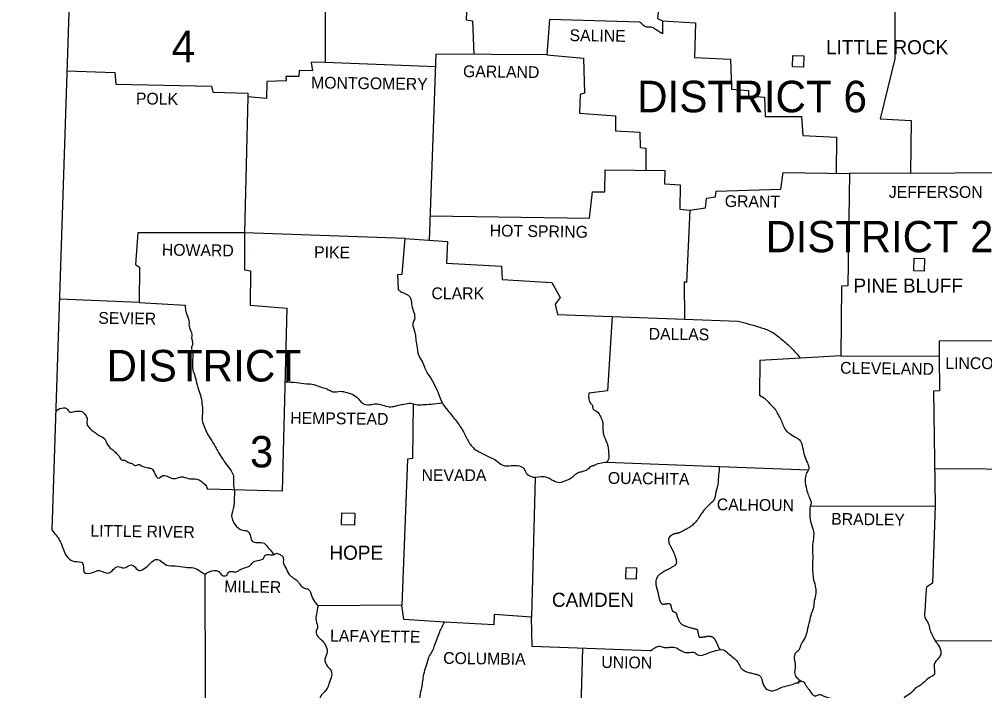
# Model space of a CAD drawing. Extents: x -819161 to 80911, y -6604 to 768454.
# Drawn here: x 48569 to 50478, y 6893 to 8220 of the extents above; entities that cross this region are included whole.
import ezdxf

# ---------------------------------------------------------------- set-up
doc = ezdxf.new("R2010")
doc.units = 0
doc.layers.add('Default', color=7, linetype='Continuous')
doc.layers.add('SHET_Border-Lines', color=7, linetype='Continuous')

msp = doc.modelspace()

# ---------------------------------------------------------------- linework, layer by layer
at = {"layer": 'Default'}
msp.add_line((48650, 7450.6), (48640.9, 7444.9), dxfattribs=at)
for points in [[(48569, 9606.7), (48682.3, 8696.4), (48633.2, 7210.7)], [(49174.7, 8359.8), (49174, 8135.6), (49146.3, 8135), (49148.8, 8118.8), (49122.4, 8119.1), (49121.8, 8107), (49095.9, 8107), (49096.5, 8098.6), (49058.6, 8097.3), (49057.6, 8064), (49020.6, 8067.4), (49014.4, 7797.9)], [(50267.6, 8353.4), (50299.4, 8351.6), (50300, 8142.1), (50271.4, 8023.6), (50332.4, 8020.5), (50331.4, 7916)], [(50014, 8298.7), (49974.8, 8303.3), (49976.3, 8288.4), (49904.4, 8285.6), (49902.3, 8264.4), (49834.7, 8260.7), (49831, 8222.1), (49841, 8217.1), (49841, 8191.9)], [(49453.5, 8234.3), (49452.6, 8219.3), (49465.3, 8217.1), (49467.6, 8150.7)], [(49795.8, 8215), (49617.2, 8220.2), (49612.2, 8149.9), (49392.8, 8151.2), (49379.3, 7783.7)], [(49841, 8217.1), (49906.3, 8213.1), (49903.8, 8144.6), (49975.4, 8141.8), (49977, 8082.1), (50010.6, 8079.3), (50010.6, 8069), (50042.6, 8066.5), (50043.6, 8028.2), (50115.8, 8028.2), (50118.3, 7990.3), (50184.9, 7987.2), (50184.5, 7915.9)], [(49174, 8135.6), (49391.9, 8127.1)], [(49612.2, 8149.9), (49684.7, 8143.7), (49686.9, 8074.6), (49677.9, 8071.8), (49676.6, 8035.1), (49748.2, 8029.8), (49748.2, 7999.6), (49795.8, 7997.1), (49796.8, 7967.2), (49808, 7965.4), (49807.6, 7922)], [(48663.2, 8118.5), (48757.6, 8115.4), (48760.1, 8092.3), (48949.3, 8088.3), (48951.5, 8076.5), (49020.6, 8074.3), (49020.6, 8067.4)], [(50837.8, 7978.7), (50630.5, 7984.7), (50629.3, 7917.1), (50210.4, 7915.6)], [(49381.1, 7831.9), (49696.2, 7827.2), (49702.2, 7879.5), (49727.1, 7879.2), (49727.7, 7923), (49845.6, 7921.5), (49845, 7895), (49875.5, 7892.9), (49875.2, 7844.9), (49895.1, 7843.1)], [(49895.1, 7843.1), (49925.6, 7847.7), (49927.8, 7866.4), (49945.8, 7869.5), (49947.1, 7880.4), (50074.7, 7884.5), (50079.7, 7917.4), (50210.4, 7915.6)], [(50210.4, 7915.6), (50207.6, 7693.4), (50194.5, 7692.4), (50193.3, 7555.2)], [(49895.1, 7843.1), (49888.6, 7699.9), (49883.9, 7701.5), (49884.2, 7627.5)], [(49331.8, 7787), (49014.4, 7797.9), (48803.7, 7798.2), (48799, 7735.7), (48806.5, 7730.4), (48806.2, 7660.1), (48648.3, 7667.3)], [(49014.4, 7797.9), (49014.4, 7725.1), (49026.5, 7722.9), (49025.3, 7655.1), (49098.1, 7649.2), (49089.1, 7287.5), (48940.3, 7291)], [(49318.8, 7685.3), (49317.2, 7715.5), (49326.2, 7716.1), (49331.8, 7787), (49415.8, 7781.1), (49414, 7737.9), (49522.6, 7732), (49523.5, 7705.8), (49621.9, 7699.9), (49638.7, 7670.3), (49628.4, 7657), (49633.4, 7636.7), (49884.2, 7627.5)], [(48806.2, 7660.1), (48896.7, 7655.1)], [(50551.8, 7643.3), (50548.7, 7563), (50535.9, 7562.7), (50533.4, 7584.4), (50387.8, 7584.1), (50388, 7554.3)], [(49741.1, 7632.8), (49732.4, 7485.5), (49695, 7481.1)], [(49884.2, 7627.5), (49990.3, 7623.7)], [(50113.6, 7550.4), (50033.3, 7545.5), (50032.7, 7477.1)], [(50193.3, 7555.2), (50113.6, 7550.4)], [(50193.3, 7555.2), (50388, 7554.3)], [(50388, 7554.3), (50388.7, 7485.5), (50376.9, 7485.2), (50380.3, 7258)], [(49347.7, 7460.2), (49346.4, 7351.7), (49336.5, 7350.4), (49325.6, 7061.9)], [(49731, 7344.7), (49953.9, 7336.4), (50129.5, 7329.6)], [(50379.2, 7332.4), (50581.6, 7330.5), (50739.4, 7318.7)], [(49588.9, 7314.3), (49581.7, 7038), (49508, 7043.2), (49507.3, 7023), (49410, 7028.6)], [(50132.6, 7257.4), (50380.3, 7258)], [(50380.3, 7258), (50375, 7105.5), (50362.6, 7097.7)], [(48935.6, 7122.6), (48936.9, 6679.4), (50943.9, 6676)], [(49410, 7028.6), (49329.3, 7033.3), (49325.6, 7061.9), (49159.7, 7060.4)], [(49816.7, 6971.4), (49583.3, 6980.1), (49581.7, 7038)], [(50380.1, 6991.6), (50739.7, 6991.9)], [(49682.6, 6976.4), (49674.3, 6678.2)]]:
    msp.add_lwpolyline(points, dxfattribs=at)
for points in [[(50097.7, 8126.3), (50098.3, 8149), (50120.4, 8148.4), (50119.8, 8125.6)], [(50337.7, 7722.9), (50338.3, 7747.8), (50358.8, 7747.2), (50358.2, 7722.3)], [(49206.4, 7221), (49207, 7244.3), (49232.2, 7243.7), (49231.6, 7220.3)], [(49768.5, 7113.9), (49769.1, 7136.6), (49789.3, 7136), (49788.7, 7113.3)]]:
    msp.add_lwpolyline(points, close=True, dxfattribs=at)
for points in [[(49841, 8191.9), (49827, 8200.3), (49818.2, 8205), (49809.8, 8204.7), (49802.7, 8209), (49795.8, 8215)], [(49318.8, 7685.3), (49327.2, 7680), (49337.7, 7675), (49343.3, 7666.9), (49345.2, 7654.2), (49349.2, 7640.5), (49350.2, 7626.5), (49347.1, 7618.7), (49351.4, 7601.3), (49353, 7589.1), (49354.9, 7575.1), (49358.9, 7555.8), (49366.1, 7542.7), (49372.6, 7526.9), (49383.5, 7509.4), (49393.1, 7491.1), (49397.5, 7481.4), (49405.6, 7461.2), (49415.8, 7447.2), (49432.7, 7426.3), (49447.3, 7404.9), (49455.4, 7389), (49468.1, 7371.6), (49482.4, 7362.9), (49500.5, 7353.8), (49512, 7347.9), (49524.8, 7338.6), (49541.9, 7338), (49554.3, 7338), (49566.2, 7332.7), (49571.5, 7323), (49581.4, 7316.2), (49588.9, 7314.3)], [(48896.7, 7655.1), (48899.5, 7638.6), (48904.5, 7624), (48904.8, 7613.4), (48910.1, 7596.9), (48909.8, 7591), (48911.7, 7578.5), (48909.5, 7572.3), (48912, 7559.2), (48911.7, 7549), (48911.4, 7540.9), (48912.3, 7527.2), (48916.4, 7515), (48920.7, 7497.3), (48923.5, 7487.7), (48928.2, 7473.3), (48930.7, 7455.9), (48931.3, 7443.2), (48930.4, 7431), (48933.8, 7417.3), (48939.7, 7403.6), (48947.2, 7390.6), (48956.5, 7375.6), (48963, 7363.8), (48971.1, 7351.3), (48977.7, 7341.1), (48987.9, 7327.7), (48992.3, 7316.8), (48992.3, 7301.9), (48994.5, 7287.2), (48993.8, 7271.7), (48992.9, 7257.1), (48988.9, 7237.8), (48991.4, 7228.4), (49001.9, 7214.7), (49008.5, 7210.7), (49020, 7208.5), (49025.3, 7200.7), (49028.7, 7189.5), (49040.2, 7185.5), (49053, 7184.5), (49059.2, 7177.7), (49067.3, 7169), (49072.2, 7161.7)], [(49990.3, 7623.7), (50033.3, 7611.5), (50055.1, 7603.1), (50076.9, 7587.2), (50094.9, 7571.4), (50113.6, 7550.4)], [(49094.5, 7503.8), (49117.4, 7502), (49136.7, 7499.8), (49151.3, 7498.2), (49166.6, 7492.9), (49180.6, 7488), (49189.3, 7483.9), (49203.9, 7484.9), (49216.7, 7482.4), (49230.7, 7477.4), (49241.3, 7468.1), (49248.1, 7460.9), (49260.6, 7458.1), (49271.1, 7460), (49283.6, 7458.7), (49297.6, 7454.7), (49309.4, 7455), (49318.8, 7457.2), (49329.6, 7459.6), (49343, 7461.2), (49353.3, 7458.7), (49367, 7458.4), (49383.2, 7459.6), (49405.1, 7462)], [(49695, 7481.1), (49695, 7470.9), (49698.4, 7461.2), (49702.2, 7456.8), (49704, 7449.4), (49709, 7446.3), (49715.9, 7439.4), (49719.9, 7430.4), (49722.4, 7424.2), (49722.7, 7416.4), (49723, 7408.9), (49724.3, 7399.9), (49730.8, 7383.1), (49732.7, 7376.6), (49733.6, 7371), (49734.2, 7361.6), (49733.9, 7350.7), (49731, 7344.7)], [(50032.7, 7477.1), (50045.1, 7468.7), (50055.4, 7457.5), (50063.2, 7449.7), (50068.5, 7440), (50074.7, 7429.2), (50084.3, 7408.3), (50092.4, 7401.1), (50103.9, 7394), (50110.8, 7389.3), (50117.9, 7373.4), (50121.4, 7357.6), (50127.3, 7343.3), (50130.1, 7332.4), (50125.1, 7321.5), (50123.9, 7299.7), (50127.6, 7284.4), (50131.6, 7273.9), (50134.4, 7261.1), (50132.6, 7257.4)], [(48650, 7450.6), (48662.1, 7450.9), (48669.9, 7443.8), (48675.2, 7444.4), (48683.6, 7445.6), (48692.3, 7445), (48697.9, 7440), (48702.9, 7431.6), (48702.6, 7423.2), (48702.9, 7419.8), (48706.9, 7413), (48713.4, 7407.4), (48720.6, 7402.1), (48726.8, 7397.4), (48738, 7390.6), (48739.3, 7388.4), (48743.3, 7379.4), (48748.9, 7372.5), (48755.5, 7367.8), (48762.6, 7360.4), (48765.7, 7356.9), (48771.3, 7349.2), (48777.2, 7348.5), (48786, 7343.6), (48791.9, 7342), (48798.1, 7338), (48804.6, 7340.1), (48813, 7336.4), (48823.9, 7333.6), (48830.1, 7332.1), (48837, 7321.8), (48844.5, 7313.1), (48852.9, 7318), (48869.7, 7313.1), (48879.9, 7312.8), (48889.3, 7315.6), (48896.4, 7314.6), (48909.5, 7311.5), (48917.6, 7311.5), (48926.6, 7308.4), (48934.7, 7301.9), (48940, 7294.4), (48940.3, 7291)], [(49704, 7337.7), (49698.4, 7335.2), (49691.6, 7329.3), (49683.2, 7326.1), (49675.7, 7324), (49665.4, 7317.4), (49658.3, 7311.8), (49647.7, 7307.2), (49637.7, 7304), (49625.6, 7307.5), (49619.1, 7311.2), (49612.2, 7314.3), (49588.9, 7314.3)], [(49704, 7337.7), (49716.8, 7342.9), (49731, 7344.7)], [(50132.6, 7257.4), (50134.7, 7223.1), (50139.7, 7206.6), (50138.5, 7189.5), (50137.5, 7172.4), (50137.9, 7157.2), (50137.5, 7142.2), (50137.9, 7127), (50138.8, 7116.1), (50142.8, 7100.2), (50144.1, 7085.3), (50141, 7070.9), (50139.4, 7057.9), (50135.1, 7044.8), (50131.3, 7030.2), (50126.7, 7010.9), (50122.9, 6998.1), (50115.1, 6985.1), (50110.2, 6973.2), (50102.7, 6965.4), (50101.8, 6952.4), (50103.3, 6939.9), (50102.1, 6929), (50106.1, 6918.8), (50115.8, 6911.6)], [(48633.2, 7210.7), (48648.7, 7190.1), (48655.2, 7174.9), (48664.9, 7155.9), (48678.3, 7148.4), (48694.1, 7145.3), (48697.3, 7127), (48713.8, 7126.3), (48727.1, 7130.4), (48745.2, 7125.4), (48764.5, 7138.2), (48775.4, 7135.4), (48790.9, 7141.9), (48803.4, 7131.6), (48824.2, 7140.7), (48842.6, 7152.5), (48860, 7141.3), (48877.1, 7139.7), (48897.4, 7136.9), (48913.2, 7135.7), (48927.6, 7128.8), (48935.6, 7122.6)], [(48935.6, 7122.6), (48954.6, 7130.7), (48963.3, 7128.2), (48970.2, 7121.1), (48978.6, 7120.7), (48983, 7127.3), (48991, 7128.2), (48997.6, 7127.6), (49004.7, 7131.6), (49010.7, 7134.4), (49018.7, 7137.2), (49025, 7139.7), (49030.3, 7145.6), (49040.5, 7150.3), (49051.7, 7154.4), (49054.8, 7160), (49060.4, 7162.1), (49071.3, 7161.5), (49078.8, 7164.6), (49084.7, 7161.8), (49090, 7158.1), (49091.3, 7144.1), (49095.6, 7136.3), (49102.5, 7122.6), (49111.5, 7115.5), (49120.2, 7108.3), (49123.3, 7103.9), (49133, 7095.5), (49141, 7093), (49144.8, 7087.1), (49150.7, 7072.5), (49159.7, 7060.4)], [(50362.6, 7097.7), (50361.3, 7080.9), (50360.4, 7065), (50359.4, 7049.8), (50359.4, 7038), (50366.3, 7025.8), (50369.7, 7013.4), (50373.8, 7003.1), (50381.2, 6989.7), (50388.4, 6979.1), (50390.9, 6964.2), (50386.2, 6956.7), (50378.1, 6944.9), (50377.5, 6924.1), (50367.5, 6917.8), (50355.1, 6906.9), (50348.2, 6902), (50340.5, 6897), (50332.4, 6888.3), (50319.9, 6879.9), (50311.2, 6866.5), (50301.6, 6855.6), (50293.2, 6850.6), (50281.6, 6843.5), (50277, 6832.6), (50273.2, 6812), (50274.5, 6797.4), (50276.7, 6784), (50274.2, 6767.8), (50276.7, 6749.5), (50279.8, 6735.2), (50283.8, 6722.7), (50289.7, 6708.4), (50297.8, 6695.6), (50312.9, 6677.1)], [(49159.7, 7060.4), (49156.6, 7044.2), (49155.7, 7031.4), (49158.5, 7017.1), (49155.7, 7009.6), (49160, 6999.4), (49168.4, 6991.3), (49174.3, 6982.6), (49178.1, 6969.5), (49173.4, 6955.5), (49178.7, 6940.9), (49183.7, 6935.3), (49186.8, 6926.2), (49182.4, 6909.7), (49177.8, 6897), (49166.9, 6884.5), (49163.8, 6878.3), (49165.3, 6870.2), (49168.1, 6857.1), (49165, 6853.1), (49158.2, 6843.8), (49155.7, 6833.5), (49150.7, 6824.5), (49145.7, 6808.9), (49138.6, 6795.5), (49137.3, 6780.6), (49126.1, 6780.9), (49114, 6780.6), (49102.1, 6772.8), (49091.9, 6772.2), (49079.1, 6766.9), (49071.3, 6756.6), (49068.8, 6745.1), (49065.4, 6734.2), (49068.5, 6715.5), (49073.5, 6702.5), (49077.6, 6691.9), (49082.8, 6679.2)], [(49360.5, 6874), (49363.3, 6891.4), (49366.1, 6905.4), (49367.9, 6918.1), (49371, 6933.1), (49376, 6949), (49380.4, 6962), (49386.3, 6971.4), (49390, 6982.3), (49395, 6995.6), (49400.3, 7009), (49410, 7028.6)], [(49816.7, 6971.4), (49825.7, 6977.6), (49833.8, 6980.7), (49842.2, 6978.8), (49850.6, 6978.2), (49858.4, 6979.1), (49868.3, 6977.3), (49876.4, 6972.6), (49885.8, 6968.6), (49895.1, 6968.6), (49903.2, 6968.6), (49910.7, 6963.6), (49923.4, 6964.2), (49934.6, 6968.6), (49945.5, 6972), (49960.5, 6973.5), (49973.2, 6964.5), (49982.9, 6956.7), (49990.3, 6948), (49995.9, 6938.1), (50002.2, 6932.5), (50011.8, 6928.7), (50019.6, 6926.9), (50028.6, 6924.4), (50033.6, 6921.9), (50038, 6911.9), (50045.1, 6897.3), (50059.1, 6892.6), (50075.6, 6899.2), (50089.6, 6902.9), (50099.6, 6906), (50105.2, 6908.2), (50110.8, 6909.1), (50109.5, 6910.1), (50115.8, 6911.6), (50122, 6907.2), (50125.7, 6901.3), (50132.3, 6892.3), (50138.2, 6884.8), (50144.1, 6882.4), (50150.6, 6885.5), (50158.4, 6882.7), (50165.6, 6880.2), (50174, 6877.7), (50180.8, 6877.4), (50190.5, 6875.2), (50197.3, 6871.1), (50203.8, 6867.1), (50210.7, 6860.3), (50217.2, 6849.1), (50219.4, 6840.3), (50226.9, 6831.6), (50234.3, 6831.6), (50244.3, 6817.6), (50248.3, 6812), (50256.4, 6802.4), (50262.3, 6802.1), (50274.1, 6800.2)]]:
    msp.add_spline(points, degree=3, dxfattribs=at)
msp.add_open_spline([(49953.2, 7336.4), (49952.3, 7325.2), (49951.4, 7314), (49950.5, 7302.8), (49950.3, 7299.9), (49949.6, 7297.1), (49948.8, 7294.3), (49948.4, 7292.9), (49948, 7291.6), (49947.6, 7290.2), (49947.2, 7288.8), (49946.8, 7287.4), (49946.5, 7286), (49945.8, 7283.4), (49945.6, 7280.7), (49945.1, 7278.1), (49944.9, 7276.8), (49944.6, 7275.5), (49944.3, 7274.2), (49944.1, 7273.5), (49943.9, 7272.9), (49943.6, 7272.3), (49943.5, 7272), (49943.3, 7271.7), (49943.2, 7271.3), (49943.1, 7271), (49942.9, 7270.7), (49942.7, 7270.4), (49942.2, 7269.5), (49941.6, 7268.7), (49940.9, 7267.9), (49940.3, 7267.2), (49939.6, 7266.5), (49938.8, 7265.8), (49938.1, 7265.1), (49937.3, 7264.5), (49936.5, 7263.8), (49935.8, 7263.1), (49935, 7262.4), (49934.3, 7261.7), (49932.9, 7260.2), (49931.4, 7258.7), (49930, 7257.2), (49928.5, 7255.7), (49927.1, 7254.2), (49925.6, 7252.7), (49922.7, 7249.7), (49920.3, 7246.4), (49917.8, 7243), (49917.1, 7242.1), (49916.5, 7241.1), (49915.9, 7240.1), (49915.3, 7239.1), (49914.7, 7238.1), (49914.1, 7237.1), (49913.5, 7236.1), (49912.9, 7235.1), (49912.3, 7234.1), (49911.7, 7233.1), (49911, 7232.2), (49910.4, 7231.2), (49908.2, 7228.3), (49905.8, 7225.7), (49903.2, 7223.1), (49900.4, 7220.4), (49897.5, 7217.7), (49894.2, 7215.7), (49891, 7213.8), (49887.8, 7212.1), (49884.5, 7210.4), (49881.2, 7208.7), (49878, 7207), (49874.6, 7205.4), (49873.7, 7205), (49872.7, 7204.6), (49871.7, 7204.4), (49870.7, 7204.1), (49869.7, 7203.9), (49868.7, 7203.7), (49867.7, 7203.5), (49866.7, 7203.3), (49865.7, 7203.1), (49864.7, 7202.9), (49863.7, 7202.6), (49862.7, 7202.3), (49861.2, 7201.7), (49859.7, 7201), (49858.3, 7200.1), (49857.6, 7199.7), (49857, 7199.2), (49856.4, 7198.6), (49856, 7198.3), (49855.8, 7198), (49855.5, 7197.7), (49855.2, 7197.4), (49854.9, 7197), (49854.7, 7196.7), (49854, 7195.7), (49853.5, 7194.6), (49853.2, 7193.5), (49852.8, 7192.3), (49852.7, 7191.1), (49852.8, 7190), (49853, 7187.7), (49853.4, 7185.4), (49854.3, 7183.3), (49855, 7181.7), (49855.7, 7180.2), (49856.5, 7178.7), (49857.3, 7177.2), (49858.1, 7175.7), (49858.9, 7174.2), (49859.7, 7172.6), (49860.5, 7171.1), (49861.3, 7169.6), (49862.1, 7168.1), (49862.7, 7166.5), (49863.4, 7164.9), (49864.5, 7162.1), (49865.5, 7159.2), (49866.5, 7156.2), (49866.8, 7155.3), (49867, 7154.4), (49867.3, 7153.5), (49867.5, 7152.6), (49867.8, 7151.7), (49867.9, 7150.8), (49868.1, 7149.9), (49868.2, 7149), (49868.2, 7148), (49868.2, 7147.6), (49868.2, 7147.1), (49868.2, 7146.7), (49868.2, 7146.2), (49868.1, 7145.8), (49868, 7145.3), (49867.8, 7144.1), (49867.3, 7143), (49866.5, 7142), (49865.7, 7140.9), (49864.8, 7140.1), (49863.7, 7139.4), (49860.9, 7137.7), (49858.1, 7136), (49855.3, 7134.4), (49851.8, 7132.5), (49848.2, 7130.8), (49844.7, 7128.8), (49841.5, 7127.1), (49838.6, 7125.1), (49835.7, 7122.9), (49834.1, 7121.8), (49832.8, 7120.4), (49831.6, 7118.9), (49831, 7118.2), (49830.6, 7117.4), (49830.1, 7116.5), (49829.6, 7115.7), (49829.2, 7114.8), (49828.8, 7113.9), (49828, 7111.8), (49827.5, 7109.7), (49827.4, 7107.5), (49827.3, 7105.4), (49827.4, 7103.2), (49827.9, 7101.1), (49828.2, 7099.9), (49828.5, 7098.7), (49828.9, 7097.5), (49829.2, 7096.3), (49829.6, 7095), (49829.9, 7093.8), (49830.3, 7092.6), (49830.6, 7091.4), (49831, 7090.2), (49831.3, 7089), (49831.6, 7087.7), (49831.9, 7086.5), (49832.6, 7083.5), (49833.2, 7080.5), (49833.8, 7077.5), (49834.1, 7076.2), (49834.4, 7074.9), (49834.7, 7073.6), (49835, 7072.3), (49835.5, 7071.1), (49835.9, 7069.8), (49836.4, 7068.6), (49837.1, 7067.5), (49837.9, 7066.5), (49838.3, 7066), (49838.7, 7065.5), (49839.3, 7065.1), (49839.5, 7064.9), (49839.8, 7064.8), (49840.1, 7064.6), (49840.4, 7064.4), (49840.6, 7064.2), (49841, 7064.1), (49841.4, 7063.9), (49841.8, 7063.8), (49842.3, 7063.8), (49842.7, 7063.8), (49843.2, 7063.9), (49843.6, 7064), (49844.1, 7064), (49844.5, 7064.2), (49844.9, 7064.3), (49845.4, 7064.3), (49845.8, 7064.4), (49846.3, 7064.4), (49846.7, 7064.4), (49847.1, 7064.4), (49847.5, 7064.5), (49847.9, 7064.6), (49848.3, 7064.6), (49848.7, 7064.7), (49849.6, 7064.8), (49850.4, 7065), (49851.2, 7065.1), (49852.1, 7065.2), (49852.9, 7065.2), (49853.7, 7065), (49854.2, 7064.9), (49854.6, 7064.8), (49855, 7064.6), (49855.2, 7064.5), (49855.4, 7064.4), (49855.6, 7064.2), (49855.8, 7064.1), (49856, 7064), (49856.2, 7063.8), (49856.6, 7063.4), (49856.8, 7062.9), (49857, 7062.4), (49857.1, 7062), (49857, 7061.5), (49857.1, 7061), (49857.3, 7060.2), (49857.5, 7059.3), (49857.8, 7058.5), (49858.4, 7056.1), (49859.2, 7053.7), (49860.3, 7051.3), (49860.6, 7050.6), (49861.2, 7049.9), (49861.9, 7049.5), (49862.7, 7049.1), (49863.5, 7048.8), (49864.3, 7048.4), (49865.1, 7048), (49865.9, 7047.6), (49866.7, 7047.2), (49867.4, 7046.8), (49868, 7046.2), (49868.3, 7045.4), (49868.6, 7045), (49868.7, 7044.5), (49868.8, 7044.1), (49868.8, 7043.6), (49868.9, 7043.1), (49869, 7042.6), (49869.1, 7042.2), (49869.1, 7041.7), (49869.2, 7041.2), (49869.3, 7040.7), (49869.4, 7040.3), (49869.6, 7039.8), (49870.2, 7038), (49871, 7036.2), (49871.8, 7034.4), (49872.5, 7032.6), (49873.5, 7030.9), (49874.6, 7029.2), (49876.6, 7026.2), (49879.1, 7023.5), (49882.4, 7022.1), (49884.4, 7021.2), (49886.5, 7020.6), (49888.6, 7019.9), (49892.7, 7018.6), (49896.9, 7017.4), (49901, 7016.2), (49903.2, 7015.6), (49905.4, 7015.2), (49907.6, 7014.6), (49907.9, 7014.5), (49908.2, 7014.4), (49908.5, 7014.2), (49909.4, 7013.5), (49910.1, 7012.6), (49910.3, 7011.5), (49910.6, 7009.8), (49910.9, 7008), (49911.2, 7006.3), (49911.6, 7004.6), (49911.9, 7002.9), (49912.2, 7001.2), (49912.4, 7000.5), (49912.7, 7000), (49913.3, 6999.5), (49913.8, 6999), (49914.4, 6998.8), (49915, 6998.7), (49916.5, 6998.6), (49917.9, 6998.6), (49919.4, 6998.8), (49920.8, 6999), (49922.3, 6999.1), (49923.7, 6999.4), (49924.8, 6999.6), (49925.8, 6999.8), (49926.9, 7000), (49927.9, 7000.2), (49928.9, 7000.4), (49930, 7000.6), (49931.8, 7000.9), (49933.8, 7000.8), (49935.6, 7000.4), (49936.6, 7000.2), (49937.5, 6999.9), (49938.4, 6999.5), (49938.9, 6999.3), (49939.3, 6999), (49939.8, 6998.7), (49940.3, 6998.5), (49940.7, 6998.2), (49941.2, 6997.8), (49942.3, 6996.9), (49943.3, 6995.9), (49944, 6994.7), (49944.6, 6993.6), (49945.3, 6992.4), (49945.8, 6991.3), (49946.3, 6990.4), (49946.8, 6989.4), (49947.2, 6988.5), (49947.6, 6987.6), (49948, 6986.6), (49948.5, 6985.7), (49948.9, 6984.7), (49949.3, 6983.8), (49949.7, 6982.9), (49950.1, 6981.9), (49950.6, 6981), (49951.1, 6980.1), (49952.2, 6978.1), (49953.1, 6976), (49954.5, 6974.3)], degree=3, dxfattribs=at)
at = {"layer": 'SHET_Border-Lines'}
msp.add_line((49028.1, 7759.3), (49028.1, 7759.3), dxfattribs=at)

# ---------------------------------------------------------------- texts
at = {"layer": 'Default'}
for s, height, p in [('4', 62.4, (48870.2, 8135.6)), ('LITTLE ROCK', 28.009, (50164.3, 8151.2)), ('DISTRICT 6', 62.43, (49790.6, 8036.5)), ('JEFFERSON', 23.34, (50288.3, 7867.3)), ('DISTRICT 2', 61.88, (50044.5, 7759.8)), ('PINE BLUFF', 28.01, (50218.5, 7679.8)), ('CLARK', 23.34, (49384, 7666.9)), ('DISTRICT', 62.43, (48741.4, 7504.2)), ('LINCOLN', 23.34, (50400, 7528.7)), ('3', 61.9, (49025.1, 7334.4)), ('NEVADA', 23.34, (49364.4, 7307.2)), ('HOPE', 28.01, (49182.2, 7151.6)), ('CAMDEN', 28.01, (49622.2, 7058.5))]:
    msp.add_text(s, height=height, dxfattribs=at).set_placement(p)
for s, height, rotation, p in [('SALINE', 23.34, 359.1885, (49656.9, 8177.3)), ('GARLAND', 23.34, 359.2717, (49446.3, 8106.1)), ('MONTGOMERY', 23.34, 359.2707, (49145.9, 8083.7)), ('POLK', 23.34, 359.3233, (48799.5, 8052.2)), ('GRANT', 23.34, 359.3139, (49963.9, 7849.3)), ('HOT SPRING', 23.34, 359.1956, (49499.1, 7791.1)), ('HOWARD', 23.34, 359.303, (48850.8, 7753.2)), ('PIKE', 23.34, 359.1737, (49151.8, 7748.5)), ('SEVIER', 23.34, 359.1815, (48725.1, 7618.4)), ('DALLAS', 23.34, 359.2802, (49813.4, 7587)), ('CLEVELAND', 23.34, 359.2412, (50191.9, 7519.7)), ('HEMPSTEAD', 23.34, 359.2571, (49104.6, 7420.8)), ('OUACHITA', 23.34, 359.2027, (49732.7, 7301.9)), ('CALHOUN', 23.34, 359.2686, (49948.1, 7249.6)), ('BRADLEY', 23.34, 359.2655, (50174.3, 7221)), ('LITTLE RIVER', 23.341, 359.2076, (48709.5, 7197.6)), ('MILLER', 23.34, 359.1885, (48974.1, 7087.5)), ('LAFAYETTE', 23.34, 359.2511, (49183.4, 6990)), ('COLUMBIA', 23.34, 359.2105, (49407.1, 6945.9)), ('UNION', 23.34, 359.2015, (49719.7, 6937.8))]:
    msp.add_text(s, height=height, rotation=rotation, dxfattribs=at).set_placement(p)

doc.saveas('drawing.dxf')
